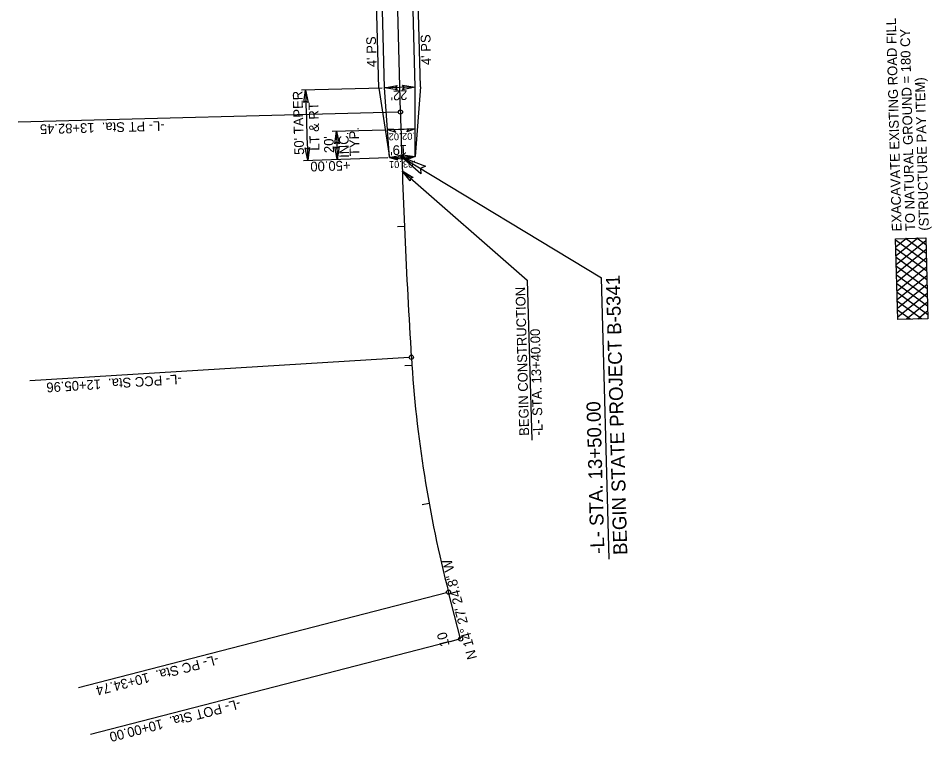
# Model space of a CAD drawing. Extents: x 1835351 to 1836442, y 993887 to 995358.
# Drawn here: x 1835618 to 1836275, y 993887 to 994407 of the extents above; entities that cross this region are included whole.
import ezdxf

# ---------------------------------------------------------------- set-up
doc = ezdxf.new("R2010")
doc.units = 0
for name, color, linetype in [('Prop Dimension', 7, 'Continuous'), ('Prop Dimension Text', 7, 'Continuous'), ('Prop EOT', 7, 'Continuous'), ('Prop Horizontal Alignment', 7, 'Continuous'), ('Prop Horizontal Alignment Direction Label', 7, 'Continuous'), ('Prop Horizontal Alignment Station Label', 7, 'Continuous'), ('Prop Horizontal Alignment Tick Label', 7, 'Continuous'), ('Prop Horizontal Alignment Tick Large', 7, 'Continuous'), ('Prop Horizontal Alignment Tick Small', 7, 'Continuous'), ('Prop Lane Lines', 7, 'Continuous'), ('Prop Paved Shoulder', 7, 'Continuous'), ('Prop Superelevation  Arrow CELL', 7, 'Continuous'), ('Prop Superelevation Label', 7, 'Continuous'), ('Prop Terminator CELL', 7, 'Continuous')]:
    doc.layers.add(name, color=color, linetype=linetype)

msp = doc.modelspace()

# ---------------------------------------------------------------- linework, layer by layer
at = {"layer": 'Prop Dimension'}
for p, q in [((1835879.87, 994357.21), (1835822.02, 994355.66)), ((1835824.92, 994355.72), (1835825.4, 994338.18)), ((1835903.62, 994357.85), (1835881.63, 994357.26)), ((1835844.06, 994326.12), (1835882.35, 994327.24)), ((1835823.37, 994305.22), (1835883.97, 994307.24)), ((1835885.18, 994307.28), (1835903.7, 994307.89)), ((1835894.41, 994297.58), (1835984.35, 994219.04)), ((1836271.45, 994231.88), (1836249.32, 994247.93)), ((1836257.15, 994249.04), (1836249.46, 994242.8)), ((1836265.36, 994249.26), (1836249.63, 994236.5)), ((1836271.28, 994238.19), (1836256.34, 994249.02)), ((1836271.11, 994244.49), (1836264.55, 994249.24)), ((1836271.62, 994225.58), (1836249.49, 994241.63)), ((1836271.03, 994247.43), (1836249.8, 994230.2)), ((1836271.8, 994219.28), (1836249.66, 994235.33)), ((1836271.2, 994241.13), (1836249.98, 994223.9)), ((1836271.37, 994234.83), (1836250.15, 994217.6)), ((1836271.97, 994212.98), (1836249.84, 994229.03)), ((1836271.54, 994228.53), (1836250.32, 994211.3)), ((1836272.14, 994206.68), (1836250.01, 994222.73)), ((1836271.72, 994222.23), (1836250.49, 994205)), ((1835984.35, 994219.04), (1835987.49, 994104.02)), ((1836272.31, 994200.38), (1836250.18, 994216.43)), ((1836271.89, 994215.93), (1836250.66, 994198.7)), ((1836272.48, 994194.08), (1836250.35, 994210.13)), ((1836272.06, 994209.63), (1836250.84, 994192.39)), ((1836267.86, 994191.26), (1836250.52, 994203.83)), ((1836272.23, 994203.32), (1836257.01, 994190.97)), ((1836259.65, 994191.04), (1836250.7, 994197.53)), ((1836272.4, 994197.02), (1836265.22, 994191.19))]:
    msp.add_line(p, q, dxfattribs=at)
for radius, start in [(5067.71, 181.53384), (5046.39, 181.6765)]:
    msp.add_arc((1840891.3, 994473.84), radius, start, 181.90568, dxfattribs=at)
at = {"layer": 'Prop Dimension Text'}
for p in [(1835894.07, 994307.57), (1836043.25, 994018.48)]:
    msp.add_line(p, (1836037.73, 994220.88), dxfattribs=at)
msp.add_lwpolyline([(1836250.88, 994190.8), (1836249.3, 994248.83), (1836270.97, 994249.42), (1836272.56, 994191.39)], close=True, dxfattribs=at)
at = {"layer": 'Prop EOT'}
for p, q in [((1835881.63, 994357.26), (1835877.99, 994493.02)), ((1835903.62, 994357.85), (1835899.98, 994493.61)), ((1835885.18, 994307.28), (1835881.63, 994357.26)), ((1835903.7, 994307.89), (1835903.62, 994357.85))]:
    msp.add_line(p, q, dxfattribs=at)
at = {"layer": 'Prop Horizontal Alignment'}
for p, q in [((1835893.09, 994340.01), (1835881.78, 994762.31)), ((1835936.37, 993961.21), (1835927.69, 993994.84))]:
    msp.add_line(p, q, dxfattribs=at)
for centre, radius, start, end in [((1840891.3, 994473.84), 5000, 181.53384, 183.55622), ((1836799.2, 994219.53), 900, 183.55622, 194.4569)]:
    msp.add_arc(centre, radius, start, end, dxfattribs=at)
at = {"layer": 'Prop Horizontal Alignment Station Label'}
for p, q in [((1835891.59, 994339.97), (1835618.19, 994332.65)), ((1835899.43, 994163.61), (1835626.46, 994146.65)), ((1835926.24, 993994.47), (1835661.4, 993926.19)), ((1835934.91, 993960.83), (1835670.07, 993892.55))]:
    msp.add_line(p, q, dxfattribs=at)
for centre in [(1835893.09, 994340.01), (1835900.93, 994163.7), (1835927.69, 993994.84), (1835936.37, 993961.21)]:
    msp.add_circle(centre, 1.5, dxfattribs=at)
at = {"layer": 'Prop Horizontal Alignment Tick Large'}
msp.add_line((1835936.37, 993961.21), (1835928.62, 993959.21), dxfattribs=at)
at = {"layer": 'Prop Horizontal Alignment Tick Small'}
for p, q in [((1835892.62, 994357.55), (1835887.62, 994357.42)), ((1835895.98, 994257.61), (1835890.98, 994257.39)), ((1835901.32, 994157.75), (1835896.33, 994157.41)), ((1835913.7, 994058.58), (1835908.79, 994057.68))]:
    msp.add_line(p, q, dxfattribs=at)
at = {"layer": 'Prop Paved Shoulder'}
for p, q in [((1835877.63, 994357.15), (1835875.97, 994418.95)), ((1835907.62, 994357.95), (1835905.96, 994419.75)), ((1835877.63, 994357.15), (1835885.18, 994307.28)), ((1835907.62, 994357.95), (1835903.7, 994307.89))]:
    msp.add_line(p, q, dxfattribs=at)
at = {"layer": 'Prop Superelevation  Arrow CELL'}
for p, q in [((1835883.76, 994327.28), (1835895.75, 994327.63)), ((1835903.67, 994327.86), (1835891.67, 994327.51)), ((1835885.18, 994307.28), (1835897.18, 994307.68)), ((1835903.7, 994307.89), (1835891.71, 994307.49))]:
    msp.add_line(p, q, dxfattribs=at)
for points in [[(1835883.76, 994327.28), (1835889.82, 994325.46), (1835888.38, 994327.42)], [(1835903.67, 994327.86), (1835897.73, 994325.69), (1835899.04, 994327.73)], [(1835885.18, 994307.28), (1835891.25, 994305.48), (1835889.81, 994307.43)], [(1835903.7, 994307.89), (1835897.77, 994305.7), (1835899.08, 994307.74)]]:
    msp.add_lwpolyline(points, close=True, dxfattribs=at)
at = {"layer": 'Prop Superelevation Label'}
msp.add_line((1835883.76, 994327.28), (1835903.67, 994327.86), dxfattribs=at)
at = {"layer": 'Prop Terminator CELL'}
for points in [[(1835823.62, 994346.69), (1835824.92, 994355.72), (1835826.77, 994346.72), (1835825.14, 994347.83)], [(1835890.66, 994355.95), (1835881.63, 994357.26), (1835890.63, 994359.1), (1835889.52, 994357.47)], [(1835894.58, 994359.16), (1835903.62, 994357.85), (1835894.61, 994356.01), (1835895.72, 994357.64)], [(1835845.79, 994317.16), (1835847.07, 994326.21), (1835848.94, 994317.21), (1835847.3, 994318.31)], [(1835827.64, 994314.37), (1835826.39, 994305.32), (1835824.49, 994314.31), (1835826.13, 994313.22)], [(1835848.95, 994315.08), (1835847.7, 994306.03), (1835845.8, 994315.02), (1835847.44, 994313.93)], [(1835894.23, 994306.03), (1835885.18, 994307.28), (1835894.17, 994309.18), (1835893.08, 994307.54)], [(1835907.88, 994295.62), (1835894.07, 994307.57), (1835911.22, 994300.96), (1835907.59, 994299.41)], [(1835894.65, 994309.14), (1835903.7, 994307.89), (1835894.71, 994305.99), (1835895.8, 994307.63)], [(1835900.17, 994290.49), (1835894.41, 994297.58), (1835902.28, 994292.83), (1835900.36, 994292.38)]]:
    msp.add_lwpolyline(points, close=True, dxfattribs=at)

# ---------------------------------------------------------------- texts
at = {"layer": 'Prop Dimension Text'}
for s, height, rotation, p in [('EXACAVATE EXISTING ROAD FILL', 7, 91.56434, (1836253.63, 994254.23)), ('TO NATURAL GROUND = 180 CY', 7, 91.56434, (1836263.42, 994254.5)), ('(STRUCTURE PAY ITEM)', 7, 91.56434, (1836273.22, 994254.76)), ("50' TAPER", 7, 91.56434, (1835823.84, 994309.28)), ('LT & RT', 7, 91.56434, (1835834.9, 994312.26)), ('TYP.', 7, 91.56434, (1835863.67, 994308.42)), ("20'", 7, 91.56434, (1835845.3, 994310.59)), ('INC.', 7, 91.56434, (1835856.18, 994307.13)), ('+50.00', 7, 181.90568, (1835857.04, 994305.14)), ('BEGIN STATE PROJECT B-5341', 10, 91.56434, (1836056.3, 994021.74)), ('BEGIN CONSTRUCTION', 7, 91.56434, (1835985.69, 994107.3)), ('-L- STA. 13+40.00', 7, 91.56434, (1835995.49, 994107.56)), ('-L- STA. 13+50.00', 10, 91.56434, (1836039.84, 994022.54))]:
    msp.add_text(s, height=height, rotation=rotation, dxfattribs=at).set_placement(p)
at = {"layer": 'Prop Horizontal Alignment Direction Label'}
msp.add_text('N 14%%d 27\' 24.8" W', height=7, rotation=104.4569, dxfattribs=at).set_placement((1835948.17, 993947.49))
at = {"layer": 'Prop Horizontal Alignment Station Label'}
for s, rotation, p in [('-L- PT Sta.  13+82.45', 181.53384, (1835723.4, 994333.46)), ('-L- PCC Sta.  12+05.96', 183.55622, (1835735.6, 994151.43)), ('-L- PC Sta.  10+34.74', 194.4569, (1835761.37, 993949.9)), ('-L- POT Sta.  10+00.00', 194.4569, (1835777.19, 993918.1))]:
    msp.add_text(s, height=7, rotation=rotation, dxfattribs=at).set_placement(p)
at = {"layer": 'Prop Horizontal Alignment Tick Label'}
msp.add_text('10', height=7, rotation=104.4569, dxfattribs=at).set_placement((1835928.54, 993956.63))
at = {"layer": 'Prop Lane Lines'}
for s, rotation, p in [('.02', 181.6192, (1835893.85, 994324.8)), ('.02', 181.6192, (1835903.5, 994325.12)), ('.01', 181.56434, (1835894.07, 994304.86)), ('.03', 181.56434, (1835904.12, 994305.12))]:
    msp.add_text(s, height=5, rotation=rotation, dxfattribs=at).set_placement(p)
at = {"layer": 'Prop Terminator CELL'}
for s, rotation, p in [("4' PS", 91.53384, (1835876.03, 994372.32)), ("4' PS", 91.53384, (1835915.21, 994373.79)), ("22'", 181.56434, (1835898.03, 994355.66)), ("19'", 181.90568, (1835897.8, 994316.31))]:
    msp.add_text(s, height=7, rotation=rotation, dxfattribs=at).set_placement(p)

doc.saveas('drawing.dxf')
